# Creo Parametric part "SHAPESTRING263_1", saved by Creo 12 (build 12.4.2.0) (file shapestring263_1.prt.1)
Units: Custom; MM, KILOGRAM, SECS

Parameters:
  PTC_WM_ITERATION = "0"
  PTC_WM_VERSION = "-.0"
  PTC_WM_LIFECYCLE_STATE = "In Work"
  PTC_WM_LIFECYCLE = "MO_CADDocument"
  PTC_WM_CREATED_BY = "Maximilian Roepper (Z0017RMS: MO)"
  PTC_WM_CREATED_ON = "18-Sep-26 11:36:42 AM"
  PTC_WM_MODIFIED_BY = "Maximilian Roepper (Z0017RMS: MO)"
  PTC_WM_MODIFIED_ON = "18-Sep-26 11:36:46 AM"
  PDMLINKNUMBER = "PDM000071454809"
  PTC_WM_NAME = "shapestring263_1.prt"
  PTC_WM_NUMBER = "PDM000071454809"

Other parameters: WEIGHT, WEIGHT_FACTOR, WEIGHT_ADD, _MASS_TEMP, _DIFF_TEMP, MC_ERRORS, SUPPLIER

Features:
  1. coordinate system
  2. datum plane "PRT_YZ"
  3. datum plane "PRT_XY"
  4. datum plane "PRT_XZ"
  5. coordinate system
  6. datum axis
  7. datum axis
  8. datum axis
  9. coordinate system
  10. imported feature
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
Other named items: PRT, SIEMENS_MO, DRW_VIEW_ORG, PRT_X, PRT_Y, PRT_Z, CS0, ROUGH_GROB

Layers: 00_STD_CSYS-KSYS, 01_STD_PLANES-EBENEN, 02_STD_AXES-ACHSEN, 03_STD_CSYS-KSYS, 24_IMPORT_FEAT-IMPORT_KE, WHITE

Surfaces: 1 plane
